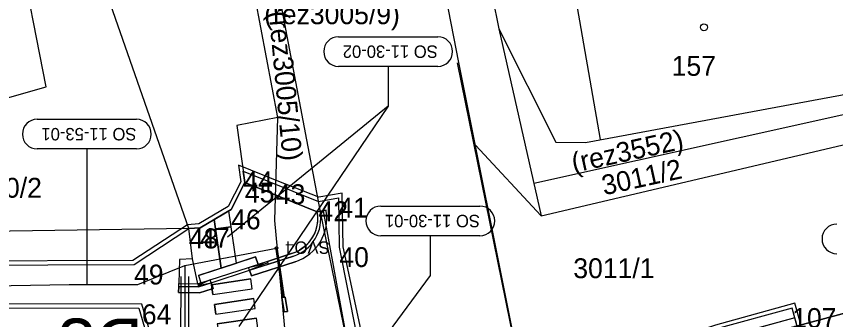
# Model space of a CAD drawing. Extents: x -728800 to -728100, y -1073200 to -1072700.
# Drawn here: x -728528.4 to -728487.13, y -1073026.38 to -1073011.1 of the extents above; entities that cross this region are included whole.
import ezdxf

# ---------------------------------------------------------------- set-up
doc = ezdxf.new("R2010")
doc.units = 0
for name, color, linetype in [('_NOR-návrh tenká', 7, 'Continuous'), ('_NOR-návrh tenká obec', 7, 'Continuous'), ('_NOR-VDZ', 7, 'Continuous'), ('_NOR-šraf_+12', 7, 'Continuous'), ('_NOR-šraf_chodník', 7, 'Continuous'), ('_NOR-šraf_signální pás', 7, 'Continuous'), ('_NOR-šraf_varovný pás', 7, 'Continuous'), ('_NOR-šraf_vozovka', 7, 'Continuous'), ('_NOR-šraf_zeleň', 7, 'Continuous'), ('A1_OBVOD Spravy železnic', 7, 'Continuous'), ('A2_OBVOD STAVBY', 7, 'Continuous'), ('B1_body_poloha', 7, 'Continuous'), ('B2_body_číslo', 7, 'Continuous'), ('K_01_Hranice parcel', 7, 'Continuous'), ('K_02_Parcelní čísla', 7, 'Continuous'), ('K_03_Značky druhu pozemku', 7, 'Continuous'), ('KOS_kabelová trasa VO', 7, 'Continuous'), ('KOS_nové prvky VO', 7, 'Continuous'), ('KTA_členění PS a SO', 7, 'Continuous'), ('ZA_02_Dočasný_do_1_roku', 7, 'Continuous')]:
    doc.layers.add(name, color=color, linetype=linetype)

msp = doc.modelspace()

# ---------------------------------------------------------------- linework, layer by layer
at = {"layer": '_NOR-návrh tenká'}
msp.add_line((-728515.702, -1073023.588), (-728515.748, -1073023.445), dxfattribs=at)
msp.add_lwpolyline([(-728489.108, -1073026.574), (-728489.188, -1073026.285), (-728493.044, -1073027.348)], dxfattribs=at)
at = {"layer": '_NOR-návrh tenká obec'}
for p, q in [((-728513.244, -1073020.944), (-728516.889, -1073019.476)), ((-728517.313, -1073023.532), (-728517.697, -1073020.9)), ((-728513.096, -1073020.917), (-728513.244, -1073020.944)), ((-728518.085, -1073023.782), (-728518.441, -1073021.342)), ((-728516.347, -1073023.219), (-728516.224, -1073023.599)), ((-728516.7, -1073023.753), (-728515.725, -1073023.516)), ((-728515.725, -1073023.516), (-728516.653, -1073023.896)), ((-728519.228, -1073024.153), (-728519.105, -1073024.534)), ((-728516.653, -1073023.896), (-728516.7, -1073023.753)), ((-728520.218, -1073024.707), (-728520.215, -1073024.557)), ((-728518.629, -1073024.379), (-728519.235, -1073024.653)), ((-728519.235, -1073024.653), (-728518.583, -1073024.522)), ((-728518.583, -1073024.522), (-728518.629, -1073024.379)), ((-728518.569, -1073024.622), (-728516.59, -1073024.333)), ((-728516.517, -1073024.828), (-728516.59, -1073024.333)), ((-728518.496, -1073025.117), (-728518.569, -1073024.622)), ((-728518.496, -1073025.117), (-728516.517, -1073024.828)), ((-728518.424, -1073025.611), (-728516.445, -1073025.322)), ((-728516.373, -1073025.817), (-728516.445, -1073025.322)), ((-728518.352, -1073026.106), (-728518.424, -1073025.611)), ((-728518.352, -1073026.106), (-728516.373, -1073025.817)), ((-728518.28, -1073026.601), (-728516.301, -1073026.312)), ((-728516.228, -1073026.807), (-728516.301, -1073026.312))]:
    msp.add_line(p, q, dxfattribs=at)
for points in [[(-728512.801, -1073020.863), (-728513.096, -1073020.917)], [(-728519.228, -1073024.153), (-728516.347, -1073023.219)], [(-728516.7, -1073023.753), (-728514.493, -1073023.037)], [(-728516.653, -1073023.896), (-728514.446, -1073023.18)], [(-728516.653, -1073023.896), (-728516.561, -1073024.181), (-728514.354, -1073023.465)], [(-728518.629, -1073024.379), (-728516.7, -1073023.753)], [(-728518.583, -1073024.522), (-728516.653, -1073023.896)], [(-728520.218, -1073024.707), (-728520.224, -1073025.007), (-728519.174, -1073025.029), (-728518.491, -1073024.807), (-728518.491, -1073024.807), (-728518.583, -1073024.522)], [(-728520.218, -1073024.707), (-728519.218, -1073024.728), (-728518.583, -1073024.522)], [(-728520.215, -1073024.557), (-728519.24, -1073024.577), (-728518.629, -1073024.379)]]:
    msp.add_lwpolyline(points, dxfattribs=at)
for radius in [1.85, 2, 2.3]:
    msp.add_arc((-728515.063, -1073021.278), radius, 287.972, 10.3872, dxfattribs=at)
at = {"layer": '_NOR-VDZ'}
for p, q in [((-728518.569, -1073024.622), (-728516.59, -1073024.333)), ((-728516.517, -1073024.828), (-728516.59, -1073024.333)), ((-728518.496, -1073025.117), (-728518.569, -1073024.622)), ((-728518.496, -1073025.117), (-728516.517, -1073024.828)), ((-728518.424, -1073025.611), (-728516.445, -1073025.322)), ((-728516.373, -1073025.817), (-728516.445, -1073025.322)), ((-728518.352, -1073026.106), (-728518.424, -1073025.611)), ((-728518.352, -1073026.106), (-728516.373, -1073025.817)), ((-728518.28, -1073026.601), (-728516.301, -1073026.312)), ((-728516.228, -1073026.807), (-728516.301, -1073026.312))]:
    msp.add_line(p, q, dxfattribs=at)
for points in [[(-728502.909, -1073029.566), (-728502.929, -1073029.468), (-728506.181, -1073013.442)], [(-728512.949, -1073020.89), (-728510.942, -1073031.839)], [(-728518.496, -1073025.117), (-728516.517, -1073024.828), (-728516.59, -1073024.333), (-728518.569, -1073024.622), (-728518.496, -1073025.117), (-728518.496, -1073025.117)], [(-728518.352, -1073026.106), (-728516.373, -1073025.817), (-728516.445, -1073025.322), (-728518.424, -1073025.611), (-728518.352, -1073026.106), (-728518.352, -1073026.106)], [(-728518.207, -1073027.096), (-728516.228, -1073026.807), (-728516.301, -1073026.312), (-728518.28, -1073026.601), (-728518.207, -1073027.096), (-728518.207, -1073027.096)]]:
    msp.add_lwpolyline(points, dxfattribs=at)
at = {"layer": '_NOR-šraf_+12'}
for points in [[(-728513.244, -1073020.944), (-728513.096, -1073020.917)], [(-728515.748, -1073023.445), (-728514.493, -1073023.037)], [(-728514.446, -1073023.18), (-728515.702, -1073023.588), (-728515.725, -1073023.516), (-728515.748, -1073023.445), (-728515.748, -1073023.445)], [(-728520.218, -1073024.707), (-728520.215, -1073024.557), (-728519.251, -1073024.577), (-728519.235, -1073024.653), (-728519.218, -1073024.728), (-728520.218, -1073024.707)]]:
    msp.add_lwpolyline(points, dxfattribs=at)
for radius in [1.85, 2]:
    msp.add_arc((-728515.063, -1073021.278), radius, 287.972, 10.3872, dxfattribs=at)
at = {"layer": '_NOR-šraf_chodník'}
msp.add_line((-728513.793, -1073022.623), (-728514.141, -1073022.881), dxfattribs=at)
for points in [[(-728517.313, -1073023.532), (-728517.697, -1073020.9), (-728517.575, -1073020.827), (-728516.889, -1073019.476), (-728513.244, -1073020.944)], [(-728519.526, -1073023.322), (-728519.714, -1073021.793), (-728519.139, -1073021.757), (-728518.441, -1073021.342), (-728518.085, -1073023.782), (-728519.228, -1073024.153), (-728519.105, -1073024.534), (-728519.24, -1073024.577), (-728519.251, -1073024.577), (-728519.526, -1073023.322)], [(-728514.493, -1073023.037), (-728515.748, -1073023.445), (-728516.224, -1073023.599), (-728516.347, -1073023.219), (-728517.313, -1073023.532)]]:
    msp.add_lwpolyline(points, dxfattribs=at)
for start, end in [(313.3529, 10.3872), (287.972, 299.9219)]:
    msp.add_arc((-728515.063, -1073021.278), 1.85, start, end, dxfattribs=at)
at = {"layer": '_NOR-šraf_signální pás'}
for points in [[(-728518.373, -1073021.807), (-728517.581, -1073021.696), (-728517.697, -1073020.9), (-728518.441, -1073021.342), (-728518.373, -1073021.807)], [(-728517.581, -1073021.696), (-728518.373, -1073021.807), (-728518.085, -1073023.782), (-728517.313, -1073023.532), (-728517.581, -1073021.696)]]:
    msp.add_lwpolyline(points, dxfattribs=at)
at = {"layer": '_NOR-šraf_varovný pás'}
msp.add_lwpolyline([(-728518.629, -1073024.379), (-728516.7, -1073023.753), (-728516.224, -1073023.599), (-728516.347, -1073023.219), (-728517.313, -1073023.532), (-728518.085, -1073023.782), (-728519.228, -1073024.153), (-728519.105, -1073024.534), (-728518.629, -1073024.379)], dxfattribs=at)
at = {"layer": '_NOR-šraf_vozovka'}
for p, q in [((-728489.188, -1073026.285), (-728493.044, -1073027.348)), ((-728489.108, -1073026.574), (-728489.188, -1073026.285))]:
    msp.add_line(p, q, dxfattribs=at)
for points in [[(-728513.096, -1073020.917), (-728512.801, -1073020.863)], [(-728516.653, -1073023.896), (-728515.702, -1073023.588), (-728514.446, -1073023.18)], [(-728514.354, -1073023.465), (-728516.561, -1073024.181), (-728516.653, -1073023.896)], [(-728518.583, -1073024.522), (-728518.539, -1073024.823), (-728519.174, -1073025.029), (-728520.224, -1073025.007), (-728520.218, -1073024.707), (-728519.218, -1073024.728), (-728518.583, -1073024.522)], [(-728518.539, -1073024.823), (-728518.583, -1073024.522), (-728518.491, -1073024.807), (-728518.539, -1073024.823)]]:
    msp.add_lwpolyline(points, dxfattribs=at)
for radius in [2, 2.3]:
    msp.add_arc((-728515.063, -1073021.278), radius, 287.972, 10.3872, dxfattribs=at)
at = {"layer": '_NOR-šraf_zeleň'}
msp.add_lwpolyline([(-728520.215, -1073024.557), (-728519.251, -1073024.577), (-728519.526, -1073023.322), (-728520.189, -1073023.343), (-728520.215, -1073024.557)], dxfattribs=at)
at = {"layer": 'A1_OBVOD Spravy železnic'}
msp.add_lwpolyline([(-728503.24, -1073052.34), (-728501.19, -1073037.94), (-728499.78, -1073032.61), (-728497.54, -1073030.15), (-728493.68, -1073027.94), (-728443.97, -1073014.59), (-728443.68, -1073014.51), (-728441.09, -1073023.23), (-728428.92, -1073019.94), (-728429.82, -1073016.43), (-728427.49, -1073015.84), (-728421.24, -1073014.23), (-728422.34, -1073010.27), (-728422.77, -1073008.34), (-728418.21, -1073007), (-728380.57, -1072997.2), (-728343.1, -1072987.57), (-728330.49, -1072984.52), (-728326.79, -1072988.95)], dxfattribs=at)
at = {"layer": 'A2_OBVOD STAVBY'}
for points in [[(-728509.455, -1073035.234), (-728510.689, -1073028.502), (-728511.933, -1073022.707), (-728511.986, -1073020.002), (-728513.157, -1073020.217), (-728515.255, -1073019.379), (-728517.216, -1073018.59), (-728517.096, -1073019.442), (-728517.727, -1073020.685), (-728519.2, -1073021.56), (-728519.78, -1073021.597), (-728522.531, -1073023.408), (-728531.159, -1073023.437), (-728533.997, -1073023.341), (-728538.386, -1073022.967), (-728542.291, -1073022.287), (-728547.296, -1073020.586), (-728553.966, -1073017.86)], [(-728556.425, -1073019.431), (-728548.14, -1073022.833), (-728542.882, -1073024.621), (-728538.694, -1073025.349), (-728534.14, -1073025.737), (-728532.664, -1073025.787), (-728522.232, -1073025.806), (-728521.488, -1073028.32), (-728521.545, -1073030.726), (-728521.594, -1073032.788), (-728517.755, -1073032.879), (-728517.209, -1073045.129)], [(-728488.873, -1073026.674), (-728489.181, -1073025.557), (-728493.185, -1073026.66), (-728494.705, -1073027.164), (-728496.389, -1073027.993), (-728498.589, -1073029.657), (-728499.85, -1073030.989), (-728500.962, -1073032.598), (-728501.8, -1073034.243), (-728502.009, -1073034.876), (-728501.833, -1073035.753)]]:
    msp.add_lwpolyline(points, dxfattribs=at)
at = {"layer": 'B1_body_poloha'}
for p, q in [((-728516.97, -1073018.91), (-728516.97, -1073018.91)), ((-728516.89, -1073019.48), (-728516.89, -1073019.48)), ((-728515.33, -1073019.56), (-728515.33, -1073019.56)), ((-728513.18, -1073020.42), (-728513.18, -1073020.42)), ((-728512.18, -1073020.24), (-728512.18, -1073020.24)), ((-728517.58, -1073020.83), (-728517.58, -1073020.83)), ((-728519.71, -1073021.79), (-728519.71, -1073021.79)), ((-728519.14, -1073021.76), (-728519.14, -1073021.76)), ((-728512.13, -1073022.73), (-728512.13, -1073022.73)), ((-728522.47, -1073023.61), (-728522.47, -1073023.61)), ((-728522.08, -1073025.61), (-728522.08, -1073025.61)), ((-728489.32, -1073025.8), (-728489.32, -1073025.8))]:
    msp.add_line(p, q, dxfattribs=at)
at = {"layer": 'K_01_Hranice parcel'}
for p, q in [((-728513.08, -1073020.94), (-728518.016, -1072994.823)), ((-728506.11, -1073013.42), (-728508.77, -1072999.931)), ((-728515.236, -1073016.2), (-728517.179, -1073005.828)), ((-728519.714, -1073021.793), (-728525.091, -1073006.333)), ((-728504.103, -1073011.723), (-728501.963, -1073021.145)), ((-728501.19, -1073037.94), (-728506.11, -1073013.42)), ((-728499.729, -1073017.446), (-728475.783, -1073013.02)), ((-728515.38, -1073021.39), (-728515.236, -1073016.2)), ((-728510.71, -1073032.54), (-728513.08, -1073020.94)), ((-728514.39, -1073031.91), (-728515.38, -1073021.39))]:
    msp.add_line(p, q, dxfattribs=at)
for points in [[(-728508.888, -1072988.018), (-728504.103, -1073011.723), (-728501.22, -1073017.439), (-728499.729, -1073017.446)], [(-728515.236, -1073016.2), (-728517.295, -1073016.589), (-728516.889, -1073019.476), (-728517.575, -1073020.827), (-728519.139, -1073021.757), (-728519.714, -1073021.793), (-728542.221, -1073022.127), (-728593.93, -1072991.26)], [(-728505.274, -1073017.588), (-728501.963, -1073021.145), (-728471.605, -1073014.006), (-728430.395, -1073002.044)], [(-728502.335, -1073019.509), (-728476.083, -1073013.675), (-728460.554, -1073010.421), (-728462.891, -1073003.585)], [(-728498.981, -1073017.308), (-728500.719, -1073007.26), (-728483.236, -1073004.236), (-728481.681, -1073014.11)], [(-728540.332, -1073009.948), (-728538.355, -1073017.863), (-728535.002, -1073016.936), (-728534.351, -1073017.951), (-728533.616, -1073018.472), (-728532.371, -1073018.702), (-728531.47, -1073018.542), (-728530.537, -1073017.994), (-728529.78, -1073016.821), (-728529.681, -1073015.434), (-728526.895, -1073014.649), (-728528.333, -1073007.34)], [(-728443.97, -1073014.59), (-728493.68, -1073027.94), (-728497.54, -1073030.15), (-728499.78, -1073032.61)]]:
    msp.add_lwpolyline(points, dxfattribs=at)
at = {"layer": 'K_03_Značky druhu pozemku'}
msp.add_circle((-728493.764, -1073011.647), 0.175, dxfattribs=at)
at = {"layer": 'KOS_kabelová trasa VO'}
for p, q in [((-728520.126, -1073029.729), (-728520.105, -1073024.204)), ((-728519.726, -1073029.73), (-728519.705, -1073024.205))]:
    msp.add_line(p, q, dxfattribs=at)
for points in [[(-728561.457, -1073013.169), (-728562.506, -1073015.027), (-728558.898, -1073016.89), (-728555.929, -1073018.337), (-728552.96, -1073019.584), (-728550.284, -1073020.683), (-728547.718, -1073021.71), (-728545.504, -1073022.477), (-728542.587, -1073023.454), (-728538.54, -1073024.158), (-728535.432, -1073024.48), (-728532.705, -1073024.598), (-728529.651, -1073024.677), (-728525.747, -1073024.604), (-728522.277, -1073024.607), (-728519.905, -1073023.659), (-728515.301, -1073022.774)], [(-728519.905, -1073023.659), (-728519.931, -1073030.624), (-728519.35, -1073030.638), (-728519.331, -1073029.784)]]:
    msp.add_lwpolyline(points, dxfattribs=at)
at = {"layer": 'KOS_nové prvky VO'}
for p, q in [((-728515.331, -1073022.834), (-728514.978, -1073025.253)), ((-728515.256, -1073022.823), (-728514.902, -1073025.242))]:
    msp.add_line(p, q, dxfattribs=at)
msp.add_lwpolyline([(-728514.917, -1073025.994), (-728515.024, -1073025.266), (-728514.856, -1073025.241), (-728514.749, -1073025.969)], close=True, dxfattribs=at)
msp.add_lwpolyline([(-728514.749, -1073025.969), (-728514.856, -1073025.241), (-728515.024, -1073025.266), (-728514.917, -1073025.994), (-728514.749, -1073025.969)], dxfattribs=at)
msp.add_circle((-728515.301, -1073022.774), 0.0665, dxfattribs=at)
at = {"layer": 'KTA_členění PS a SO'}
for p, q in [((-728509.672, -1073013.622), (-728509.672, -1073015.622)), ((-728509.672, -1073015.622), (-728517.759, -1073022.219)), ((-728509.672, -1073015.622), (-728517.188, -1073026.72)), ((-728524.851, -1073017.78), (-728524.858, -1073024.605)), ((-728507.548, -1073022.158), (-728507.548, -1073024.158)), ((-728507.548, -1073024.158), (-728512.902, -1073031.401))]:
    msp.add_line(p, q, dxfattribs=at)
for points in [[(-728512.172, -1073012.122), (-728507.172, -1073012.122)], [(-728507.172, -1073013.622), (-728512.172, -1073013.622)], [(-728527.351, -1073016.28), (-728522.351, -1073016.28)], [(-728522.351, -1073017.78), (-728527.351, -1073017.78)], [(-728510.048, -1073020.658), (-728505.048, -1073020.658)], [(-728505.048, -1073022.158), (-728510.048, -1073022.158)]]:
    msp.add_lwpolyline(points, dxfattribs=at)
for centre, start, end in [((-728512.166, -1073012.872), 90.4529, 269.5471), ((-728507.178, -1073012.872), 270.4529, 89.5471), ((-728527.345, -1073017.03), 90.4529, 269.5471), ((-728522.357, -1073017.03), 270.4529, 89.5471), ((-728510.042, -1073021.408), 90.4529, 269.5471), ((-728505.054, -1073021.408), 270.4529, 89.5471), ((-728487.068, -1073022.314), 90.4529, 269.5471)]:
    msp.add_arc(centre, 0.75, start, end, dxfattribs=at)
at = {"layer": 'ZA_02_Dočasný_do_1_roku'}
for points in [[(-728531.162, -1073023.637), (-728526.817, -1073023.623), (-728522.471, -1073023.608), (-728519.714, -1073021.793), (-728519.139, -1073021.757), (-728517.575, -1073020.827), (-728516.889, -1073019.476), (-728516.969, -1073018.905), (-728513.177, -1073020.424), (-728512.181, -1073020.241), (-728512.132, -1073022.73), (-728509.606, -1073035.517), (-728510.327, -1073035.465), (-728509.415, -1073042.185), (-728509.9, -1073046.86), (-728517.01, -1073045.12), (-728517.286, -1073038.902), (-728517.563, -1073032.683), (-728521.389, -1073032.592), (-728521.287, -1073028.294), (-728522.083, -1073025.607), (-728532.66, -1073025.587)], [(-728489.068, -1073026.719), (-728489.321, -1073025.803), (-728493.127, -1073026.851)]]:
    msp.add_lwpolyline(points, dxfattribs=at)

# ---------------------------------------------------------------- texts
at = {"layer": 'B2_body_číslo'}
for s, p in [('44', (-728516.97, -1073019.91)), ('45', (-728516.89, -1073020.48)), ('43', (-728515.33, -1073020.56)), ('42', (-728513.18, -1073021.42)), ('41', (-728512.18, -1073021.24)), ('46', (-728517.58, -1073021.83)), ('48', (-728519.71, -1073022.79)), ('47', (-728519.14, -1073022.76)), ('40', (-728512.13, -1073023.73)), ('49', (-728522.47, -1073024.61)), ('64', (-728522.08, -1073026.61)), ('107', (-728489.32, -1073026.8))]:
    msp.add_text(s, height=1, dxfattribs=at).set_placement(p)
at = {"layer": 'K_02_Parcelní čísla'}
for s, p in [('(rez3005/9)', (-728515.918, -1073011.492)), ('157', (-728495.392, -1073014.092)), ('80/2', (-728529.716, -1073020.235)), ('3011/1', (-728500.346, -1073024.291))]:
    msp.add_text(s, height=1, dxfattribs=at).set_placement(p)
for s, rotation, p in [('(rez3005/10)', 275.3761, (-728515.69, -1073010.867)), ('(rez3552)', 12.3696, (-728500.314, -1073018.985)), ('3011/2', 12.3696, (-728498.794, -1073020.12))]:
    msp.add_text(s, height=1, rotation=rotation, dxfattribs=at).set_placement(p)
at = {"layer": 'KOS_nové prvky VO'}
msp.add_text('SVO4', height=0.625, rotation=180, dxfattribs=at).set_placement((-728512.622, -1073022.439))
at = {"layer": 'KTA_členění PS a SO'}
for s, p in [('SO 11-30-02', (-728507.173, -1073012.564)), ('SO 11-53-01', (-728522.352, -1073016.722)), ('SO 11-30-01', (-728505.049, -1073021.099))]:
    msp.add_text(s, height=0.625, rotation=180, dxfattribs=at).set_placement(p)
at = {"layer": 'ZA_02_Dočasný_do_1_roku'}
msp.add_text('D3', height=2.5, rotation=180, dxfattribs=at).set_placement((-728522.024, -1073026.326))

doc.saveas('drawing.dxf')
